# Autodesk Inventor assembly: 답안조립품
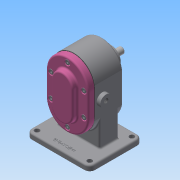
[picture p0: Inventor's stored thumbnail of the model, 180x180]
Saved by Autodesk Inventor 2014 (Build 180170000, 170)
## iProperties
Created: 2020-09
Part Number: 답안조립품
Document SubType Name: Assembly
Designer: NET
Author: NET
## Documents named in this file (11)
- C:\Users\NET\Desktop\700906v1033\답안조립품.iam
- C:\Users\NET\Desktop\700906v1033\본체.ipt
- C:\Users\NET\Desktop\700906v1033\개스킷.ipt
- C:\Users\NET\Desktop\700906v1033\메인축.ipt
- C:\Users\NET\Desktop\700906v1033\베어링부시.ipt
- C:\Users\NET\Desktop\700906v1033\볼트 M5.ipt
- C:\Users\NET\Desktop\700906v1033\서브축.ipt
- C:\Users\NET\Desktop\700906v1033\스퍼기어.ipt
- C:\Users\NET\Desktop\700906v1033\오일 실 16 28 7.ipt
- C:\Users\NET\Desktop\700906v1033\커버.ipt
- C:\Users\NET\Desktop\700906v1033\키 6 x 6 x 18.ipt
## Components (1 placed, 1 different names)
1. 개스킷:1
